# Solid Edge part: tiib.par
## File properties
Author: Romil
Template: iso part.par
Last saved by: Romil
Revision: 70
Application: Solid Edge
Accuracy: 0.990
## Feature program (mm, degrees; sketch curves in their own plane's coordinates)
sketch for "unnamed Protrusion 1" plane through (0, 0, 0) normal (1, 0, 0) x-axis (0, 1, 0)
  line (19.9939, -3.6062) -> (19.6938, -3.6056)
  line (19.6938, -3.6056) -> (11.993, -3.5906)
extrude "unnamed Protrusion 1" add finite 64 along -normal
sketch for "unnamed Cutout 1" #1 plane through (0, 0, 0) normal (1, 0, 0) x-axis (0, 1, 0)
  circle centre (-8.3934, 10.3983) radius 3.6
sketch for "unnamed Cutout 1" #2 plane through (0, 0, 0) normal (1, 0, 0) x-axis (0, 1, 0)
  circle centre (8.4, 10.4) radius 3.6
sketch for "unnamed Cutout 1" #3 plane through (0, 0, 0) normal (1, 0, 0) x-axis (0, 1, 0)
  circle centre (20.0008, -0.0062) radius 2.4
sketch for "unnamed Cutout 1" #4 plane through (0, 0, 0) normal (1, 0, 0) x-axis (0, 1, 0)
  circle centre (12, 0.0094) radius 2.4
sketch for "unnamed Cutout 1" #5 plane through (0, 0, 0) normal (1, 0, 0) x-axis (0, 1, 0)
  circle centre (-12, 0) radius 2.4
sketch for "unnamed Cutout 1" #6 plane through (0, 0, 0) normal (1, 0, 0) x-axis (0, 1, 0)
  circle centre (-20.0022, -0.0077) radius 2.4
extrude "unnamed Cutout 1" cut finite 98.4 along -normal
sketch for "unnamed Cutout 2" plane through (-77.5854, 0, 0) normal (1, 0, 0) x-axis (0, 1, 0)
  arc centre (-8.3934, 10.3983) radius 4.5 from (-3.9051, 10.0742) to (-12.324, 8.2073) cw
  arc centre (-2.5011, -17.1296) radius 27.1744 from (-19.5068, 4.066) to (-12.324, 8.2073) cw
  line (-19.5068, 4.066) -> (-21.2147, 6.1947)
  line (-21.2147, 6.1947) -> (-28.4759, -2.4589)
  line (-28.4759, -2.4589) -> (-28.4759, -4.9022)
  line (-28.4759, -4.9022) -> (0, -4.9022)
  line (28.4759, -4.9022) -> (0, -4.9022)
  line (28.4759, -2.4589) -> (28.4759, -4.9022)
  line (21.2147, 6.1947) -> (28.4759, -2.4589)
  line (19.5068, 4.066) -> (21.2147, 6.1947)
  arc centre (2.5011, -17.1296) radius 27.1744 from (19.5068, 4.066) to (12.3239, 8.2073) ccw
  arc centre (8.3933, 10.3983) radius 4.5 from (3.905, 10.0742) to (12.3239, 8.2073) ccw
  arc centre (-0.0001, -31.1003) radius 41.3592 from (-3.9051, 10.0742) to (3.905, 10.0742) cw
extrude "unnamed Cutout 2" cut along +normal
sketch for "unnamed Cutout 3" plane through (0, 0, 0) normal (1, 0, 0) x-axis (0, 1, 0)
  arc centre (8.0937, 5.6077) radius 0.3 from (8.3937, 5.608) to (8.1125, 5.9071) ccw
  arc centre (8.3933, 10.3983) radius 4.5 from (8.1125, 5.9071) to (3.905, 10.0742) cw
  arc centre (-0.0001, -31.1003) radius 41.3592 from (-3.9051, 10.0742) to (3.905, 10.0742) cw
  arc centre (-8.3934, 10.3983) radius 4.5 from (-3.9051, 10.0742) to (-8.1125, 5.9071) cw
  arc centre (-8.0937, 5.6077) radius 0.3 from (-8.1125, 5.9071) to (-8.3937, 5.608) ccw
  line (-8.4, 0.0094) -> (-8.3937, 5.608)
  arc centre (0, 0) radius 8.4 from (-8.4, 0.0094) to (8.4, 0.0094) cw
  line (8.4, 0.0094) -> (8.3937, 5.608)
extrude "unnamed Cutout 3" cut along +normal
sketch for "unnamed Cutout 4" #1 plane through (0, 0, 0) normal (1, 0, 0) x-axis (0, 1, 0)
  arc centre (-8.3934, 10.3983) radius 4.5 from (-9.6125, 6.0666) to (-12.1979, 7.995) cw
  arc centre (-12.4516, 7.8348) radius 0.3 from (-12.1979, 7.995) to (-12.5626, 8.1135) ccw
  arc centre (-2.5011, -17.1296) radius 27.1744 from (-12.5626, 8.1135) to (-15.6587, 6.647) ccw
  arc centre (-15.5134, 6.3845) radius 0.3 from (-15.6587, 6.647) to (-15.7588, 6.2119) ccw
  line (-13.7873, 3.4096) -> (-15.7588, 6.2119)
  arc centre (-13.542, 3.5822) radius 0.3 from (-13.7873, 3.4096) to (-13.4234, 3.3067) ccw
  arc centre (-9.6937, 3.145) radius 0.3 from (-9.8711, 2.9031) to (-9.3937, 3.145) ccw
  line (-9.3937, 5.22) -> (-9.3937, 3.145)
  line (-9.3937, 5.22) -> (-9.3937, 5.7778)
  arc centre (-9.6937, 5.7778) radius 0.3 from (-9.3937, 5.7778) to (-9.6125, 6.0666) ccw
sketch for "unnamed Cutout 4" #2 plane through (0, 0, 0) normal (1, 0, 0) x-axis (0, 1, 0)
  arc centre (-2.5011, -17.1296) radius 27.1744 from (-17.0544, 5.8193) to (-19.5068, 4.066) ccw
  arc centre (-19.3191, 3.832) radius 0.3 from (-19.5068, 4.066) to (-19.3716, 3.5367) ccw
  arc centre (-20.0022, -0.0077) radius 3.6 from (-19.3716, 3.5367) to (-16.4803, 0.7379) cw
  arc centre (-16.1868, 0.8) radius 0.3 from (-16.4803, 0.7379) to (-16.1868, 0.5) ccw
  line (-15.8171, 0.5) -> (-16.1868, 0.5)
  arc centre (-15.8171, 0.8) radius 0.3 from (-15.8171, 0.5) to (-15.5234, 0.7385) ccw
  arc centre (-12, 0) radius 3.6 from (-15.5234, 0.7385) to (-14.6313, 2.4569) cw
  arc centre (-14.8506, 2.6616) radius 0.3 from (-14.6313, 2.4569) to (-14.6052, 2.8342) ccw
  line (-16.6484, 5.7385) -> (-14.6052, 2.8342)
  arc centre (-16.8938, 5.5659) radius 0.3 from (-16.6484, 5.7385) to (-17.0544, 5.8193) ccw
sketch for "unnamed Cutout 4" #3 plane through (0, 0, 0) normal (1, 0, 0) x-axis (0, 1, 0)
  line (-16.1836, -0.5) -> (-15.8171, -0.5)
  arc centre (-15.8171, -0.8) radius 0.3 from (-15.5234, -0.7385) to (-15.8171, -0.5) ccw
  arc centre (-12, 0) radius 3.6 from (-11.9965, -3.6) to (-15.5234, -0.7385) cw
  line (-11.9965, -3.6) -> (-19.9988, -3.6077)
  arc centre (-16.1836, -0.8) radius 0.3 from (-16.1836, -0.5) to (-16.4773, -0.7391) ccw
sketch for "unnamed Cutout 4" #4 plane through (0, 0, 0) normal (1, 0, 0) x-axis (0, 1, 0)
  arc centre (12, 0) radius 3.6 from (11.9965, -3.6) to (15.5234, -0.7385) ccw
  arc centre (15.8171, -0.8) radius 0.3 from (15.5234, -0.7385) to (15.8171, -0.5) cw
  line (16.1836, -0.5) -> (15.8171, -0.5)
  arc centre (16.1836, -0.8) radius 0.3 from (16.1836, -0.5) to (16.4773, -0.7391) cw
  arc centre (20.0022, -0.0077) radius 3.6 from (16.4773, -0.7391) to (19.9988, -3.6077) ccw
  line (11.9965, -3.6) -> (19.9988, -3.6077)
sketch for "unnamed Cutout 4" #5 plane through (0, 0, 0) normal (1, 0, 0) x-axis (0, 1, 0)
  line (16.6484, 5.7385) -> (14.6052, 2.8342)
  arc centre (14.8506, 2.6616) radius 0.3 from (14.6313, 2.4569) to (14.6052, 2.8342) cw
  arc centre (12, 0) radius 3.6 from (15.5234, 0.7385) to (14.6313, 2.4569) ccw
  arc centre (15.8171, 0.8) radius 0.3 from (15.8171, 0.5) to (15.5234, 0.7385) cw
  line (15.8171, 0.5) -> (16.1868, 0.5)
  arc centre (16.1868, 0.8) radius 0.3 from (16.4803, 0.7379) to (16.1868, 0.5) cw
  arc centre (20.0022, -0.0077) radius 3.6 from (19.3716, 3.5367) to (16.4803, 0.7379) ccw
  arc centre (19.3191, 3.832) radius 0.3 from (19.5068, 4.066) to (19.3716, 3.5367) cw
  arc centre (2.5011, -17.1296) radius 27.1744 from (17.0544, 5.8193) to (19.5068, 4.066) cw
  arc centre (16.8938, 5.5659) radius 0.3 from (16.6484, 5.7385) to (17.0544, 5.8193) cw
sketch for "unnamed Cutout 4" #6 plane through (0, 0, 0) normal (1, 0, 0) x-axis (0, 1, 0)
  arc centre (12.4516, 7.8348) radius 0.3 from (12.1979, 7.995) to (12.5626, 8.1135) cw
  arc centre (2.5011, -17.1296) radius 27.1744 from (12.5626, 8.1135) to (15.6587, 6.647) cw
  arc centre (15.5134, 6.3845) radius 0.3 from (15.6587, 6.647) to (15.7588, 6.2119) cw
  line (13.7873, 3.4096) -> (15.7588, 6.2119)
  arc centre (13.542, 3.5822) radius 0.3 from (13.7873, 3.4096) to (13.4234, 3.3067) cw
  arc centre (12, 0) radius 3.6 from (13.4234, 3.3067) to (9.8711, 2.9031) ccw
  arc centre (9.6937, 3.145) radius 0.3 from (9.8711, 2.9031) to (9.3937, 3.145) cw
  line (9.3937, 5.22) -> (9.3937, 3.145)
  line (9.3937, 5.22) -> (9.3937, 5.7778)
  arc centre (9.6937, 5.7778) radius 0.3 from (9.3937, 5.7778) to (9.6125, 6.0666) cw
  arc centre (8.3934, 10.3983) radius 4.5 from (9.6125, 6.0666) to (12.1979, 7.995) ccw
extrude "unnamed Cutout 4" cut
sketch for "unnamed Cutout 5" plane through (0, 0, 0) normal (1, 0, 0) x-axis (0, 1, 0)
  line (4.4627, 8.2073) -> (-4.232, 8.6858)
  arc centre (-8.3934, 10.3983) radius 4.5 from (-4.232, 8.6858) to (-10.4674, 6.4047) cw
  line (-11.3546, 5.4345) -> (-10.4674, 6.4047)
  line (-15.0528, 6.2119) -> (-11.3546, 5.4345)
  line (-15.0528, 15.2951) -> (-15.0528, 6.2119)
  line (-15.0528, 15.2951) -> (11.8477, 16.9874)
  line (11.8477, 16.9874) -> (15.0528, 13.1985)
  line (15.0528, 13.1985) -> (12.7504, 11.5239)
extrude "unnamed Cutout 5" cut along +normal
sketch for "unnamed Cutout 6" plane through (0, 0, 0) normal (1, 0, 0) x-axis (0, 1, 0)
  arc centre (0, 0) radius 8.4 from (-8.4, 0) to (-5.4276, 6.411) cw
  line (-5.7077, 6.7876) -> (-5.4276, 6.411)
  arc centre (-8.3934, 10.3983) radius 4.5 from (-5.7077, 6.7876) to (-11.282, 6.9477) cw
  line (-11.282, 6.9477) -> (-11.282, 3.5277)
extrude "unnamed Cutout 6" cut finite 2 along -normal
sketch for "ExtrudedCutout_85" plane through (0, 0, 0) normal (1, 0, 0) x-axis (0, 1, 0)
  arc centre (2.8787, -16.2107) radius 27.1744 from (22.6155, 2.4683) to (12.709, 9.1234) ccw
  line (5.5033, 4.2891) -> (6.339, 6.3946)
  line (8.3957, 3.896) -> (5.5033, 4.2891)
  line (8.4, 0.0054) -> (8.3957, 3.896)
  line (11.993, -3.5906) -> (14.3039, -3.5951)
  line (14.3039, -3.5951) -> (14.519, -3.8042)
  line (14.519, -3.8042) -> (23.9524, -6.7024)
  line (23.9524, -6.7024) -> (23.6008, -0.0062)
extrude "ExtrudedCutout_85" cut finite 15.6 symmetric
sketch for "unnamed Cutout 7" plane through (0, 0, 0) normal (1, 0, 0) x-axis (0, 1, 0)
  line (12.2264, 4.8937) -> (12.5706, 3.5545)
  line (11.6184, 7.2598) -> (12.2264, 4.8937)
  arc centre (8.3934, 10.3983) radius 4.5001 from (11.6184, 7.2598) to (5.4564, 6.9888) cw
  line (5.4564, 6.9888) -> (4.724, 3.3067)
  line (4.724, 3.3067) -> (8.7652, -1.5799)
extrude "unnamed Cutout 7" cut finite 9.8 along -normal
sketch for "ExtrudedCutout_88" plane through (0, 0, 0) normal (0, 0, 1) x-axis (1, 0, 0)
  line (-35.7395, -32.543) -> (-67.2077, -33.0787)
  line (-67.2077, -33.0787) -> (-68.106, 19.6874)
  line (-67.8371, 22.1326) -> (-68.106, 19.6874)
  line (-60.4895, 22.486) -> (-67.8371, 22.1326)
  line (-63.9423, 16.5056) -> (-60.4895, 22.486)
  arc centre (-63.7691, 16.4056) radius 0.2 from (-63.9423, 16.3056) to (-63.9423, 16.5056) cw
  line (-63.9423, 16.3056) -> (-43.0665, -19.8523)
  line (-43.0665, -19.8523) -> (-35.7395, -32.543)
extrude "ExtrudedCutout_88" cut finite 15.6 along +normal
sketch used by "unnamed Cutout 8" plane through (-77.5854, 0, 0) normal (1, 0, 0) x-axis (0, 1, 0)
extrude "unnamed Cutout 8" cut along +normal
sketch for "unnamed Cutout 9" plane through (-77.5854, 0, 0) normal (1, 0, 0) x-axis (0, 1, 0)
  line (-13.9518, 7.5145) -> (-7.0892, 1.9573)
  line (-7.0892, 1.9573) -> (6.6582, 1.9573)
  line (6.6582, 1.9573) -> (14.5148, 7.245)
  arc centre (2.5011, -17.1296) radius 27.1744 from (12.9908, 7.9386) to (14.5148, 7.245) cw
  arc centre (2.5132, -16.2432) radius 26.3541 from (3.9051, 10.0741) to (12.9908, 7.9386) cw
  arc centre (-0.0001, -31.1003) radius 41.3592 from (3.9051, 10.0741) to (-3.9059, 10.0741) ccw
  arc centre (-3.0903, -13.5619) radius 23.65 from (-12.4264, 8.1674) to (-3.9059, 10.0741) cw
  arc centre (-249.8044, 560.6523) radius 601.3217 from (-12.4264, 8.1674) to (-13.9518, 7.5145) cw
extrude "unnamed Cutout 9" cut along +normal
sketch for "unnamed Cutout 10" #1 plane through (0, 0, 0) normal (1, 0, 0) x-axis (0, 1, 0)
  circle centre (-12, 0) radius 3.1
sketch for "unnamed Cutout 10" #2 plane through (0, 0, 0) normal (1, 0, 0) x-axis (0, 1, 0)
  circle centre (-20.0022, -0.0077) radius 3.1
extrude "unnamed Cutout 10" cut finite 0.9 along -normal
sketch for "unnamed Cutout 11" #1 plane through (0, 0, 0) normal (1, 0, 0) x-axis (0, 1, 0)
  circle centre (20.0008, -0.0062) radius 3.1
sketch for "unnamed Cutout 11" #2 plane through (0, 0, 0) normal (1, 0, 0) x-axis (0, 1, 0)
  circle centre (12, 0.0094) radius 3.1
extrude "unnamed Cutout 11" cut finite 8.7 along -normal
sketch for "ExtrudedCutout_98" #1 plane through (-15.6, 13.7528, 3.2341) normal (-1, 0, 0) x-axis (0, -0.999998, 0.00195)
  line (22.6465, -3.2843) -> (22.6465, -4.4419)
  arc centre (22.4965, -4.4419) radius 0.15 from (22.3552, -4.4923) to (22.6465, -4.4419) ccw
  line (22.1465, -3.2843) -> (22.1465, -9.4769)
  line (22.1465, -9.4769) -> (22.6465, -9.4769)
  line (22.6465, -9.4769) -> (28.8465, -9.4769)
  line (28.8465, -9.4769) -> (28.8465, -3.2843)
sketch for "ExtrudedCutout_98" #2 plane through (-15.6, 13.7528, 3.2341) normal (-1, 0, 0) x-axis (0, -0.999998, 0.00195)
  line (30.6487, -3.3076) -> (30.6487, -9.4769)
  line (30.6487, -9.4769) -> (36.8487, -9.4769)
  line (37.3487, -9.4769) -> (36.8487, -9.4769)
  line (37.3487, -3.3076) -> (37.3487, -9.4769)
  arc centre (36.9987, -4.4652) radius 0.15 from (36.8487, -4.4652) to (37.14, -4.5155) ccw
  line (36.8487, -4.4652) -> (36.8487, -3.3076)
extrude "ExtrudedCutout_98" cut finite 8.7 along -normal
sketch for "unnamed Cutout 12" plane through (-15.6, 13.7528, 3.2341) normal (-1, 0, 0) x-axis (0, -0.999998, 0.00195)
  line (-9.8543, -9.5171) -> (-9.3543, -9.4769)
  line (-9.3543, -9.4769) -> (-3.1543, -9.4769)
  line (-3.1543, -9.4769) -> (-3.1543, -3.2281)
  line (-9.3543, -3.2281) -> (-9.3543, -4.3857)
  arc centre (-9.5043, -4.3857) radius 0.15 from (-9.6456, -4.436) to (-9.3543, -4.3857) ccw
  line (-9.8543, -3.2281) -> (-9.8543, -9.5171)
extrude "unnamed Cutout 12" cut finite 0.9 along -normal
sketch for "ExtrudedCutout_103" plane through (-15.6, 13.7528, 3.2341) normal (-1, 0, 0) x-axis (0, -0.999998, 0.00195)
  line (5.3465, -3.2281) -> (5.3465, -9.4769)
  line (5.3465, -9.4769) -> (4.8465, -9.4769)
  line (-1.3535, -9.4769) -> (4.8465, -9.4769)
  line (-1.3535, -3.2281) -> (-1.3535, -9.4769)
  line (4.8465, -4.3857) -> (4.8465, -3.2281)
  arc centre (4.9965, -4.3857) radius 0.15 from (4.8465, -4.3857) to (5.1378, -4.4361) ccw
extrude "ExtrudedCutout_103" cut finite 0.89 along -normal
Other named dimensions: "ExtrudedSurface_3": FiniteDepth = 102.6651 mm | "ExtrudedSurface_4": FiniteDepth = 256.7365 mm | "ExtrudedSurface_5": FiniteDepth = 98.011 mm | "ExtrudedSurface_6": FiniteDepth = 85.4777 mm
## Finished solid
Body 1: sheet body, 1 face, 4 edges, 4 vertices.
  Faces by surface: plane 1
  Edges by curve: line 4
Body 2: sheet body, 3 faces, 10 edges, 8 vertices.
  Faces by surface: plane 2, cylinder 1
  Edges by curve: line 8, circle 2
Body 3: sheet body, 3 faces, 10 edges, 8 vertices.
  Faces by surface: spline 2, plane 1
  Edges by curve: line 6, spline 4
Body 4: sheet body, 3 faces, 10 edges, 8 vertices.
  Faces by surface: plane 3
  Edges by curve: line 10
Body 5: sheet body, 3 faces, 10 edges, 8 vertices.
  Faces by surface: plane 3
  Edges by curve: line 10
Body 6: sheet body, 3 faces, 10 edges, 8 vertices.
  Faces by surface: plane 3
  Edges by curve: line 10
Body 7: sheet body, 3 faces, 10 edges, 8 vertices.
  Faces by surface: plane 3
  Edges by curve: line 10
Body 8: solid body, 146 faces, 410 edges, 260 vertices.
  Faces by surface: cylinder 85, plane 56, spline 5
  Edges by curve: line 189, circle 154, ellipse 48, intersection 16, spline 3
Bounding box of the edges (mm; curved faces can reach further): 65.896 x 166.466 x 256.736, from (-63.9691, -100.6802, -128.3682) to (1.9266, 65.786, 128.3682).
Cylindrical faces by radius (mm): R0.15 x4, R0.2 x2, R0.3 x26, R2.4 x4, R3.1 x8, R3.6 x13, R4.5 x8, R4.5001 x1, R8.4 x1, R23.65 x2, R26.3541 x2, R27.1744 x8, R29.7361 x2, R36.5646 x2, R41.3592 x3
Planar faces by outward normal: +x 15, +y 2, +z 2, -x 7, -y 2, -z 3, oblique 25
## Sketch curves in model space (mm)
arc centre (-15.6, 23.2486, -1.1701) radius 0.15 from (-15.6, 23.3898, -1.2207) through (-15.6, 23.2184, -1.317) to (-15.6, 23.0986, -1.1698)
arc centre (-15.6, 20.0008, -0.0062) radius 3.6 from (-15.6, 23.6008, -0.0132) through (-15.6, 23.5471, -0.626) to (-15.6, 23.3898, -1.2207)
line (-15.6, 23.6008, -0.0132) -> (-15.6, 23.5886, -6.3022)
line (-15.6, 23.5886, -6.3022) -> (-15.6, 23.0886, -6.261)
line (-15.6, 23.0886, -6.261) -> (-15.6, 16.8886, -6.249)
line (-15.6, 16.8886, -6.249) -> (-15.6, 16.9008, -0.0002)
arc centre (-15.6, 20.0008, -0.0062) radius 3.1 from (-15.6, 16.9008, -0.0002) through (-15.6, 20.0987, 3.0923) to (-15.6, 23.1008, -0.0122)
line (-15.6, 23.1008, -0.0122) -> (-15.6, 23.0986, -1.1698)
line (-15.6, 15.0878, -6.2454) -> (-15.6, 8.8878, -6.2333)
line (-15.6, 8.3878, -6.2324) -> (-15.6, 8.8878, -6.2333)
line (-15.6, 8.4, 0.0164) -> (-15.6, 8.3878, -6.2324)
arc centre (-15.6, 12, 0.0094) radius 3.6 from (-15.6, 8.6063, -1.1919) through (-15.6, 8.4514, -0.5966) to (-15.6, 8.4, 0.0164)
arc centre (-15.6, 8.7477, -1.1419) radius 0.15 from (-15.6, 8.8977, -1.1421) through (-15.6, 8.7686, -1.2904) to (-15.6, 8.6063, -1.1919)
line (-15.6, 8.8977, -1.1421) -> (-15.6, 8.9, 0.0154)
arc centre (-15.6, 12, 0.0094) radius 3.1 from (-15.6, 8.9, 0.0154) through (-15.6, 12.0979, 3.1078) to (-15.6, 15.1, 0.0033)
line (-15.6, 15.1, 0.0033) -> (-15.6, 15.0878, -6.2454)
arc centre (-15.6, -8.7523, -1.1639) radius 0.15 from (-15.6, -8.6111, -1.2145) through (-15.6, -8.7825, -1.3108) to (-15.6, -8.9023, -1.1636)
arc centre (-15.6, -12, 0) radius 3.6 from (-15.6, -8.4, -0.007) through (-15.6, -8.4538, -0.6198) to (-15.6, -8.6111, -1.2145)
line (-15.6, -8.4, -0.007) -> (-15.6, -8.4121, -6.1996)
line (-15.6, -8.4121, -6.1996) -> (-15.6, -8.9121, -6.1986)
line (-15.6, -8.9121, -6.1986) -> (-15.6, -15.1121, -6.1865)
line (-15.6, -15.1121, -6.1865) -> (-15.6, -15.1, 0.006)
arc centre (-15.6, -12, 0) radius 3.1 from (-15.6, -15.1, 0.006) through (-15.6, -11.9021, 3.0985) to (-15.6, -8.9, -0.006)
line (-15.6, -8.9, -0.006) -> (-15.6, -8.9023, -1.1636)
line (-15.6, -16.9143, -6.183) -> (-15.6, -23.1142, -6.1709)
line (-15.6, -23.6142, -6.17) -> (-15.6, -23.1142, -6.1709)
line (-15.6, -23.6022, -0.0006) -> (-15.6, -23.6142, -6.17)
arc centre (-15.6, -20.0022, -0.0077) radius 3.6 from (-15.6, -23.3959, -1.209) through (-15.6, -23.5508, -0.6137) to (-15.6, -23.6022, -0.0006)
arc centre (-15.6, -23.2545, -1.1589) radius 0.15 from (-15.6, -23.1045, -1.1592) through (-15.6, -23.2336, -1.3075) to (-15.6, -23.3959, -1.209)
line (-15.6, -23.1045, -1.1592) -> (-15.6, -23.1022, -0.0016)
arc centre (-15.6, -20.0022, -0.0077) radius 3.1 from (-15.6, -23.1022, -0.0016) through (-15.6, -19.9043, 3.0908) to (-15.6, -16.9022, -0.0137)
line (-15.6, -16.9022, -0.0137) -> (-15.6, -16.9143, -6.183)
arc centre (-77.5854, 2.5011, -17.1296) radius 27.1744 from (-77.5854, 12.9908, 7.9386) through (-77.5854, 12.6583, 8.0752) to (-77.5854, 12.3239, 8.2073)
arc centre (-77.5854, 2.5011, -17.1296) radius 27.1744 from (-77.5854, 12.9908, 7.9386) through (-77.5854, 13.7582, 7.6035) to (-77.5854, 14.5148, 7.245)
line (-77.5854, 6.6582, 1.9573) -> (-77.5854, 14.5148, 7.245)
line (-77.5854, -7.0892, 1.9573) -> (-77.5854, 6.6582, 1.9573)
line (-77.5854, -13.9518, 7.5145) -> (-77.5854, -7.0892, 1.9573)
arc centre (-77.5854, -249.8044, 560.6523) radius 601.3217 from (-77.5854, -12.4264, 8.1674) through (-77.5854, -13.1889, 7.8404) to (-77.5854, -13.9518, 7.5145)
arc centre (-77.5854, -3.0903, -13.5619) radius 23.65 from (-77.5854, -12.4264, 8.1674) through (-77.5854, -8.2549, 9.5173) to (-77.5854, -3.9059, 10.0741)
arc centre (-77.5854, -0.0001, -31.1003) radius 41.3592 from (-77.5854, 3.9051, 10.0741) through (-77.5854, -0.0004, 10.2589) to (-77.5854, -3.9059, 10.0741)
arc centre (-77.5854, 2.5132, -16.2432) radius 26.3541 from (-77.5854, 3.9051, 10.0741) through (-77.5854, 8.5433, 9.4118) to (-77.5854, 12.9908, 7.9386)
line (-15.6, -13.0274, 9.1234) -> (1.9266, -13.0274, 30.0108)
line (-15.6, -13.0274, 4.3277) -> (-15.6, -13.0274, 9.1234)
line (-15.6, -13.0274, -13.9174) -> (-15.6, -13.0274, 4.3277)
line (-40.6062, 13.1489, 9.1234) -> (-29.9565, 13.1489, 27.5691)
line (-40.6062, 13.1489, 4.2134) -> (-40.6062, 13.1489, 9.1234)
line (-43.0665, -19.8523, 0) -> (-35.7395, -32.543, 0)
line (-35.7395, -32.543, 0) -> (-67.2077, -33.0787, 0)
line (-67.2077, -33.0787, 0) -> (-68.106, 19.6874, 0)
line (-67.8371, 22.1326, 0) -> (-68.106, 19.6874, 0)
line (-60.4895, 22.486, 0) -> (-67.8371, 22.1326, 0)
line (-63.9423, 16.5056, 0) -> (-60.4895, 22.486, 0)
arc centre (-63.7691, 16.4056, 0) radius 0.2 from (-63.9423, 16.3056, 0) through (-63.9691, 16.4056, 0) to (-63.9423, 16.5056, 0)
line (-63.9423, 16.3056, 0) -> (-43.0665, -19.8523, 0)
arc centre (-77.5854, -1.952, -18.5988) radius 29.7361 from (-77.5854, -12.709, 9.1234) through (-77.5854, -8.4004, 10.4296) to (-77.5854, -3.9439, 11.0705)
arc centre (-77.5854, -8.3934, 10.3983) radius 4.5 from (-77.5854, -12.709, 9.1234) through (-77.5854, -9.1058, 14.8416) to (-77.5854, -3.9439, 11.0705)
arc centre (-77.5854, 0.4572, -25.3276) radius 36.5646 from (-77.5854, 3.9438, 11.0705) through (-77.5854, 8.3864, 10.367) to (-77.5854, 12.709, 9.1234)
arc centre (-77.5854, 8.3933, 10.3983) radius 4.5 from (-77.5854, 3.9438, 11.0705) through (-77.5854, 9.6292, 14.7253) to (-77.5854, 12.709, 9.1234)
line (0, 5.4564, 6.9888) -> (0, 4.724, 3.3067)
line (0, 4.724, 3.3067) -> (0, 8.7652, -1.5799)
arc centre (0, 12, 0) radius 3.6 from (0, 8.7652, -1.5799) through (0, 9.1723, 2.228) to (0, 12.5706, 3.5545)
line (0, 12.2264, 4.8937) -> (0, 12.5706, 3.5545)
line (0, 11.6184, 7.2598) -> (0, 12.2264, 4.8937)
arc centre (0, 8.3934, 10.3983) radius 4.5001 from (0, 11.6184, 7.2598) through (0, 8.5911, 5.9026) to (0, 5.4564, 6.9888)
line (-15.6, -32.287, 0) -> (-15.6, -100.6802, 0)
line (-15.6, 23.6008, 0) -> (-15.6, 65.786, 0)
line (-15.6, 23.6008, 0) -> (-15.6, -32.287, 0)
line (-57.1423, 16.5056, 0) -> (-53.6895, 22.486, 0)
arc centre (-56.9691, 16.4056, 0) radius 0.2 from (-57.1423, 16.3056, 0) through (-57.1691, 16.4056, 0) to (-57.1423, 16.5056, 0)
line (-57.1423, 16.3056, 0) -> (-36.2665, -19.8523, 0)
line (-36.2665, -19.8523, 0) -> (-28.9395, -32.543, 0)
line (0, -5.7077, 6.7876) -> (0, -5.4276, 6.411)
arc centre (0, -8.3934, 10.3983) radius 4.5 from (0, -5.7077, 6.7876) through (0, -8.6532, 5.9058) to (0, -11.282, 6.9477)
line (0, -11.282, 6.9477) -> (0, -11.282, 3.5277)
arc centre (0, -12, 0) radius 3.6 from (0, -11.282, 3.5277) through (0, -9.1455, 2.1936) to (0, -8.4, 0)
arc centre (0, 0, 0) radius 8.4 from (0, -8.4, 0) through (0, -7.6208, 3.5333) to (0, -5.4276, 6.411)
arc centre (0, 8.3933, 10.3983) radius 4.5 from (0, 12.709, 9.1234) through (0, 10.1653, 6.2619) to (0, 6.339, 6.3946)
line (0, 5.5033, 4.2891) -> (0, 6.339, 6.3946)
line (0, 8.3957, 3.896) -> (0, 5.5033, 4.2891)
line (0, 8.4, 0.0054) -> (0, 8.3957, 3.896)
arc centre (0, 12, 0.0094) radius 3.6 from (0, 11.993, -3.5906) through (0, 9.3806, -2.4601) to (0, 8.4, 0.0054)
line (0, 11.993, -3.5906) -> (0, 14.3039, -3.5951)
line (0, 14.3039, -3.5951) -> (0, 14.519, -3.8042)
line (0, 14.519, -3.8042) -> (0, 23.9524, -6.7024)
line (0, 23.9524, -6.7024) -> (0, 23.6008, -0.0062)
arc centre (0, 20.0008, -0.0062) radius 3.6 from (0, 22.6155, 2.4683) through (0, 23.3454, 1.3255) to (0, 23.6008, -0.0062)
arc centre (0, 2.8787, -16.2107) radius 27.1744 from (0, 22.6155, 2.4683) through (0, 18.0321, 6.3464) to (0, 12.709, 9.1234)
line (0, -15.0528, 6.2119) -> (0, -11.3546, 5.4345)
line (0, -11.3546, 5.4345) -> (0, -10.4674, 6.4047)
arc centre (0, -8.3934, 10.3983) radius 4.5 from (0, -4.232, 8.6858) through (0, -6.8474, 6.1722) to (0, -10.4674, 6.4047)
line (0, 4.4627, 8.2073) -> (0, -4.232, 8.6858)
arc centre (0, 8.3934, 10.3983) radius 4.5001 from (0, 12.7504, 11.5239) through (0, 9.8165, 6.1292) to (0, 4.4627, 8.2073)
line (0, 15.0528, 13.1985) -> (0, 12.7504, 11.5239)
line (0, 11.8477, 16.9874) -> (0, 15.0528, 13.1985)
line (0, -15.0528, 15.2951) -> (0, 11.8477, 16.9874)
line (0, -15.0528, 15.2951) -> (0, -15.0528, 6.2119)
line (-7.8, 28.4442, 0) -> (-7.8, 15.0528, 0)
line (-7.8, 15.0528, 0) -> (0, -15.0528, 0)
line (0, -15.0528, 0) -> (0, -46.0414, 0)
line (-6.7908, -8.4198, 0) -> (-6.7908, -48.531, 0)
line (-14.6, 8.323, 0) -> (-14.6, 27.6676, 0)
line (-14.6, 8.323, 0) -> (-6.7908, -8.4198, 0)
arc centre (0, -14.8506, 2.6616) radius 0.3 from (0, -14.6313, 2.4569) through (0, -14.5508, 2.6498) to (0, -14.6052, 2.8342)
arc centre (0, -12, 0) radius 3.6 from (0, -15.5234, 0.7385) through (0, -15.1951, 1.6588) to (0, -14.6313, 2.4569)
arc centre (0, -15.8171, 0.8) radius 0.3 from (0, -15.8171, 0.5) through (0, -15.6211, 0.5728) to (0, -15.5234, 0.7385)
line (0, -15.8171, 0.5) -> (0, -16.1868, 0.5)
arc centre (0, -16.1868, 0.8) radius 0.3 from (0, -16.4803, 0.7379) through (0, -16.3687, 0.5614) to (0, -16.1868, 0.5)
arc centre (0, -20.0022, -0.0077) radius 3.6 from (0, -19.3716, 3.5367) through (0, -17.4984, 2.579) to (0, -16.4803, 0.7379)
arc centre (0, -19.3191, 3.832) radius 0.3 from (0, -19.5068, 4.066) through (0, -19.6075, 3.7493) to (0, -19.3716, 3.5367)
arc centre (0, -2.5011, -17.1296) radius 27.1744 from (0, -17.0544, 5.8193) through (0, -18.305, 4.9767) to (0, -19.5068, 4.066)
arc centre (0, -16.8938, 5.5659) radius 0.3 from (0, -16.6484, 5.7385) through (0, -16.8353, 5.8601) to (0, -17.0544, 5.8193)
line (0, -16.6484, 5.7385) -> (0, -14.6052, 2.8342)
arc centre (0, -15.5134, 6.3845) radius 0.3 from (0, -15.6587, 6.647) through (0, -15.8058, 6.4518) to (0, -15.7588, 6.2119)
line (0, -13.7873, 3.4096) -> (0, -15.7588, 6.2119)
arc centre (0, -13.542, 3.5822) radius 0.3 from (0, -13.7873, 3.4096) through (0, -13.615, 3.2913) to (0, -13.4234, 3.3067)
arc centre (0, -12, 0) radius 3.6 from (0, -13.4234, 3.3067) through (0, -11.5936, 3.577) to (0, -9.8711, 2.9031)
arc centre (0, -9.6937, 3.145) radius 0.3 from (0, -9.8711, 2.9031) through (0, -9.5502, 2.8816) to (0, -9.3937, 3.145)
line (0, -9.3937, 5.22) -> (0, -9.3937, 3.145)
line (0, -9.3937, 5.22) -> (0, -9.3937, 5.7778)
arc centre (0, -9.6937, 5.7778) radius 0.3 from (0, -9.3937, 5.7778) through (0, -9.4546, 5.9589) to (0, -9.6125, 6.0666)
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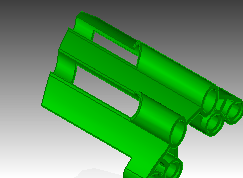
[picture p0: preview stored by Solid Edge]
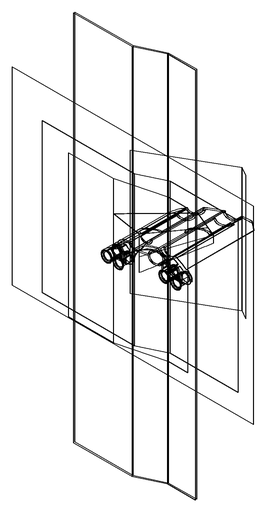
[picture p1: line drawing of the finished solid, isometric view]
